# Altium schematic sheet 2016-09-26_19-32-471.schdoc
size 246 x 132 mm; SheetNumber: 1; SheetTotal: 1
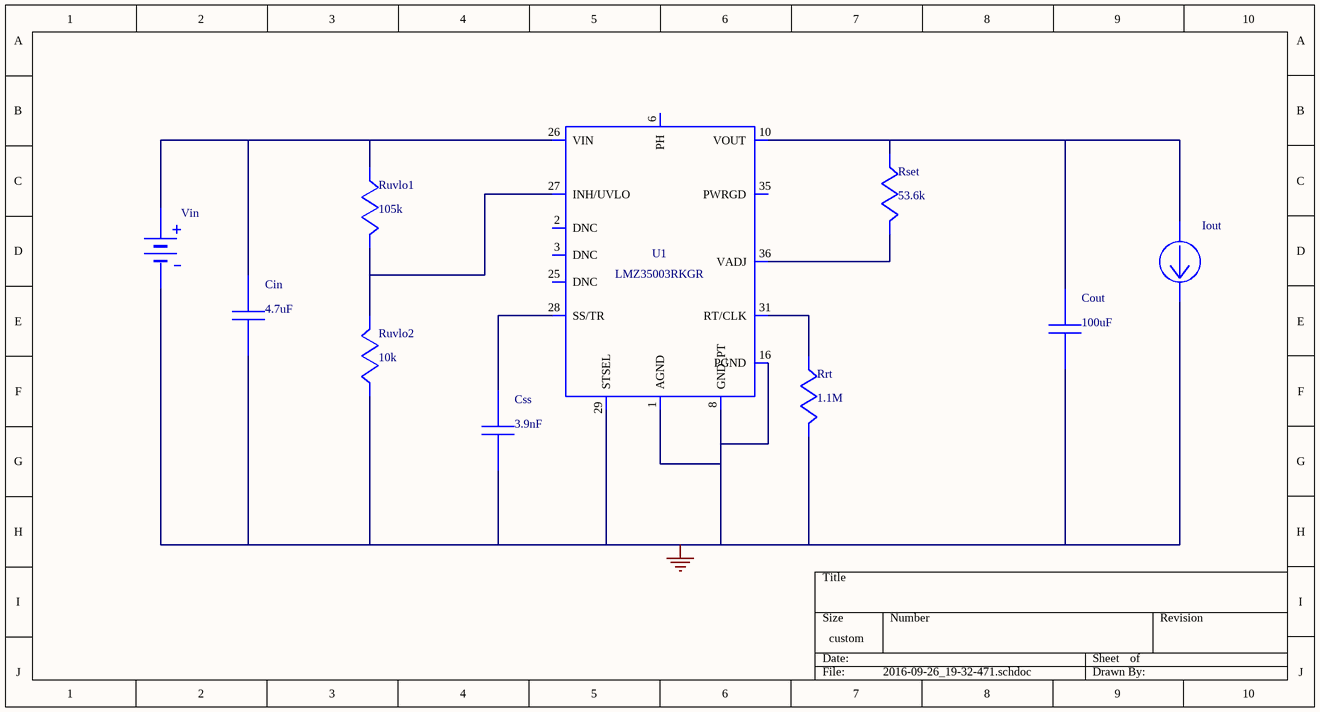
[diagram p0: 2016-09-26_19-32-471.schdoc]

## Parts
Cin  value 4.7uF  (hidden comment: GRM32ER71H475KA88L)
Cout  value 100uF  (hidden comment: GRM31CR60J107ME39L)
Css  value 3.9nF  (hidden comment: GRM033R71A392KA01D)
Iout  WB_CURRENT_LOAD  (value not drawn)
Rrt  value 1.1M  (hidden comment: CRCW04021M10FKED)
Rset  value 53.6k  (hidden comment: CRCW040253K6FKED)
Ruvlo1  value 105k  (hidden comment: CRCW0402105KFKED)
Ruvlo2  value 10k  (hidden comment: CRCW040210K0FKED)
U1  LMZ35003RKGR
Vin  WB_BATTERY  (value not drawn)

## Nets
0: Cin.2 Cout.2 Css.2 Iout.2(-) Rrt.1 Ruvlo2.2 U1.1(AGND) U1.4(AGND) U1.5(AGND) U1.8(GND_PT) U1.9(GND_PT) U1.16(PGND) U1.17(PGND) U1.18(PGND) U1.19(PGND) U1.20(PGND) U1.29(STSEL) U1.30(AGND) U1.32(AGND) U1.33(AGND) U1.34(AGND) U1.37(AGND) U1.40(PGND) Vin.2(-)
NetCin_1: Cin.1 Ruvlo1.2 U1.26(VIN) Vin.1(+)
NetCout_1: Cout.1 Iout.1(+) Rset.2 U1.10(VOUT) U1.11(VOUT) U1.12(VOUT) U1.13(VOUT) U1.14(VOUT) U1.15(VOUT) U1.39(VOUT)
NetCss_1: Css.1 U1.28(SS/TR)
NetRrt_2: Rrt.2 U1.31(RT/CLK)
NetRset_1: Rset.1 U1.36(VADJ)
NetRuvlo1_1: Ruvlo1.1 Ruvlo2.1 U1.27(INH/UVLO)
NetU1_6: U1.6(PH) U1.7(PH) U1.21(PH) U1.22(PH) U1.23(PH) U1.24(PH) U1.38(PH) U1.41(PH)

Not connected (* = marked no-connect by the designer): U1 2(DNC) 3(DNC) 25(DNC) 35(PWRGD)

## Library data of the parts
Cin = GRM32ER71H475KA88L: GRM32ER71H475KA8; Manufacturer Name: MuRata
Cout = GRM31CR60J107ME39L: GRM31CR60J107ME3; Manufacturer Name: MuRata
Css = GRM033R71A392KA01D: GRM033R71A392KA0; Manufacturer Name: MuRata
Rrt = CRCW04021M10FKED: Manufacturer Name: Vishay-Dale
Rset = CRCW040253K6FKED: Manufacturer Name: Vishay-Dale
Ruvlo1 = CRCW0402105KFKED: Manufacturer Name: Vishay-Dale
Ruvlo2 = CRCW040210K0FKED: Manufacturer Name: Vishay-Dale
U1 = LMZ35003RKGR: Manufacturer Name: Texas Instruments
